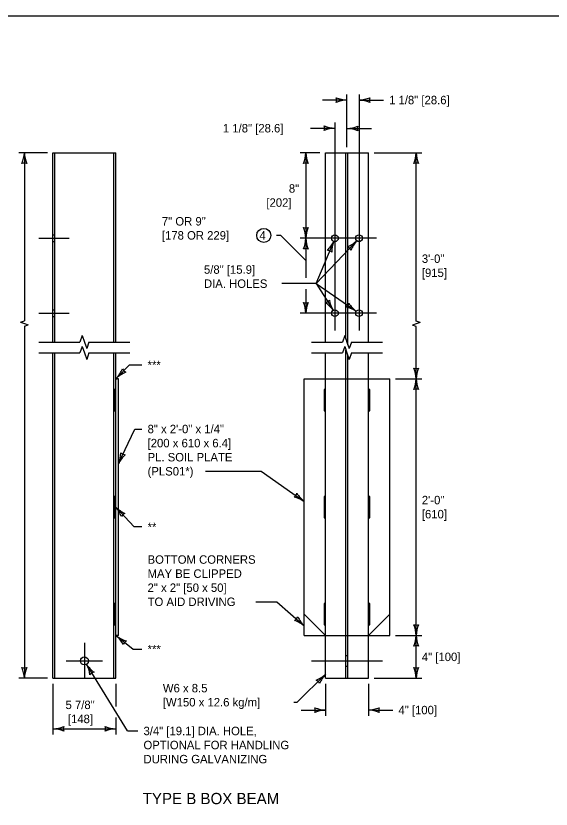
# Model space of a CAD drawing. Extents: x 49991.4 to 50021, y 49987.6 to 50011.4.
# Drawn here: x 50004.46 to 50008.26, y 49993.37 to 49999 of the extents above; entities that cross this region are included whole.
import ezdxf

# ---------------------------------------------------------------- set-up
doc = ezdxf.new("R2010")
doc.units = 0
for name, color, linetype in [('Level 1', 7, 'Continuous'), ('Level 2', 7, 'Continuous'), ('Level 3', 7, 'Continuous'), ('Level 4', 7, 'Continuous'), ('Level 5', 7, 'Continuous'), ('Level 6', 7, 'Continuous')]:
    doc.layers.add(name, color=color, linetype=linetype)

msp = doc.modelspace()

# ---------------------------------------------------------------- linework, layer by layer
at = {"layer": 'Level 1'}
for p, q in [((50004.7193, 49998.0275), (50005.1652, 49998.0275)), ((50004.7193, 49996.6835), (50004.7193, 49998.0275)), ((50004.7335, 49996.6835), (50004.7335, 49998.0275)), ((50005.151, 49996.6835), (50005.151, 49998.0275)), ((50005.1652, 49996.6835), (50005.1652, 49998.0275)), ((50006.6543, 49998.0275), (50006.9579, 49998.0275)), ((50006.6543, 49996.6835), (50006.6543, 49998.0275)), ((50006.9579, 49996.6835), (50006.9579, 49998.0275)), ((50004.7193, 49994.2976), (50004.7193, 49996.6067)), ((50004.7335, 49994.2976), (50004.7335, 49996.6067)), ((50005.151, 49994.2976), (50005.151, 49996.6067)), ((50005.1652, 49994.2976), (50005.1652, 49996.6067)), ((50006.6543, 49994.2976), (50006.6543, 49996.6067)), ((50006.9579, 49994.2976), (50006.9579, 49996.6067)), ((50005.1842, 49996.4228), (50005.1652, 49996.4228)), ((50005.1842, 49994.6012), (50005.1842, 49996.4228)), ((50006.5025, 49994.6012), (50006.5025, 49996.4228)), ((50006.5025, 49996.4228), (50006.6543, 49996.4228)), ((50006.9579, 49996.4228), (50007.1097, 49996.4228)), ((50007.1097, 49994.6012), (50007.1097, 49996.4228)), ((50005.1652, 49996.3469), (50005.1555, 49996.3469)), ((50005.1555, 49996.3469), (50005.1555, 49996.1951)), ((50005.1652, 49996.1951), (50005.1652, 49996.3469)), ((50006.6543, 49996.3469), (50006.6446, 49996.3469)), ((50006.6446, 49996.3469), (50006.6446, 49996.1951)), ((50006.6543, 49996.1951), (50006.6543, 49996.3469)), ((50006.9677, 49996.3469), (50006.9579, 49996.3469)), ((50006.9579, 49996.3469), (50006.9579, 49996.1951)), ((50006.9677, 49996.1951), (50006.9677, 49996.3469)), ((50005.1555, 49996.1951), (50005.1652, 49996.1951)), ((50006.6446, 49996.1951), (50006.6543, 49996.1951)), ((50006.9579, 49996.1951), (50006.9677, 49996.1951)), ((50005.1652, 49995.5879), (50005.1555, 49995.5879)), ((50005.1555, 49995.5879), (50005.1555, 49995.4361)), ((50005.1652, 49995.4361), (50005.1652, 49995.5879)), ((50006.6543, 49995.5879), (50006.6446, 49995.5879)), ((50006.6446, 49995.5879), (50006.6446, 49995.4361)), ((50006.6543, 49995.4361), (50006.6543, 49995.5879)), ((50006.9677, 49995.5879), (50006.9579, 49995.5879)), ((50006.9579, 49995.5879), (50006.9579, 49995.4361)), ((50006.9677, 49995.4361), (50006.9677, 49995.5879)), ((50005.1555, 49995.4361), (50005.1652, 49995.4361)), ((50006.6446, 49995.4361), (50006.6543, 49995.4361)), ((50006.9579, 49995.4361), (50006.9677, 49995.4361)), ((50005.1652, 49994.8289), (50005.1555, 49994.8289)), ((50005.1555, 49994.8289), (50005.1555, 49994.6771)), ((50005.1652, 49994.6771), (50005.1652, 49994.8289)), ((50006.6543, 49994.8289), (50006.6446, 49994.8289)), ((50006.6446, 49994.8289), (50006.6446, 49994.6771)), ((50006.6543, 49994.6771), (50006.6543, 49994.8289)), ((50006.9677, 49994.8289), (50006.9579, 49994.8289)), ((50006.9579, 49994.8289), (50006.9579, 49994.6771)), ((50006.9677, 49994.6771), (50006.9677, 49994.8289)), ((50005.1555, 49994.6771), (50005.1652, 49994.6771)), ((50006.6446, 49994.6771), (50006.6543, 49994.6771)), ((50006.9579, 49994.6771), (50006.9677, 49994.6771)), ((50005.1842, 49994.6012), (50005.1652, 49994.6012)), ((50006.5025, 49994.6012), (50006.6543, 49994.6012)), ((50006.9579, 49994.6012), (50007.1097, 49994.6012)), ((50004.7193, 49994.2976), (50005.1652, 49994.2976)), ((50006.6543, 49994.2976), (50006.9579, 49994.2976))]:
    msp.add_line(p, q, dxfattribs=at)
msp.add_lwpolyline([(49999.3835, 49998.9992), (50016.7501, 49998.9992), (50016.7501, 49987.7988), (49999.3835, 49987.7988)], close=True, dxfattribs=at)
for points in [[(50005.1652, 49996.4325), (50005.1652, 49996.4228), (50005.1749, 49996.4228), (50005.1652, 49996.4325)], [(50005.1652, 49994.5915), (50005.1652, 49994.6012), (50005.1749, 49994.6012), (50005.1652, 49994.5915)]]:
    msp.add_lwpolyline(points, dxfattribs=at)
for centre, radius in [((50006.7207, 49997.4203), 0.0237), ((50006.8915, 49997.4203), 0.0237), ((50006.7207, 49996.889), 0.0237), ((50006.8915, 49996.889), 0.0237), ((50004.9424, 49994.4207), 0.0285)]:
    msp.add_circle(centre, radius, dxfattribs=at)
at = {"layer": 'Level 2'}
msp.add_circle((50006.2154, 49997.4409), 0.05, dxfattribs=at)
at = {"layer": 'Level 3'}
for p, q in [((50006.8061, 49998.4017), (50006.6327, 49998.4017)), ((50006.8061, 49998.0675), (50006.8061, 49998.4417)), ((50006.8915, 49998.4017), (50007.065, 49998.4017)), ((50006.5473, 49998.2017), (50006.7207, 49998.2017)), ((50006.8061, 49998.1999), (50006.9796, 49998.1999)), ((50004.6793, 49998.0275), (50004.4761, 49998.0275)), ((50004.5161, 49998.0275), (50004.5161, 49996.8346)), ((50006.6143, 49998.0275), (50006.4743, 49998.0275)), ((50006.5143, 49998.0275), (50006.5143, 49997.4203)), ((50006.9979, 49998.0275), (50007.3375, 49998.0275)), ((50007.2975, 49996.8331), (50007.2975, 49998.0275)), ((50006.3366, 49997.4409), (50006.3054, 49997.4409)), ((50006.5143, 49997.2632), (50006.3366, 49997.4409)), ((50006.5143, 49997.4203), (50006.5143, 49997.1384)), ((50006.5864, 49997.0984), (50006.8752, 49997.4031)), ((50006.5864, 49997.0984), (50006.7116, 49997.3985)), ((50006.5864, 49997.0984), (50006.3443, 49997.0984)), ((50006.5143, 49997.0584), (50006.5143, 49996.889)), ((50006.5864, 49997.0984), (50006.7079, 49996.909)), ((50006.5864, 49997.0984), (50006.872, 49996.9025)), ((50004.4887, 49996.8249), (50004.5161, 49996.8346)), ((50004.4887, 49996.8249), (50004.5161, 49996.8152)), ((50007.3249, 49996.8234), (50007.2975, 49996.8331)), ((50007.3249, 49996.8234), (50007.2975, 49996.8137)), ((50004.5161, 49996.8152), (50004.5435, 49996.8055)), ((50004.5161, 49996.7958), (50004.5435, 49996.8055)), ((50004.5161, 49996.7958), (50004.5161, 49994.2976)), ((50007.2975, 49996.8137), (50007.2701, 49996.804)), ((50007.2975, 49996.7943), (50007.2701, 49996.804)), ((50007.2975, 49996.4228), (50007.2975, 49996.7943)), ((50005.2635, 49996.521), (50005.1701, 49996.4276)), ((50005.2635, 49996.521), (50005.3508, 49996.521)), ((50007.1497, 49996.4228), (50007.3375, 49996.4228)), ((50007.2975, 49994.6012), (50007.2975, 49996.4228)), ((50005.1842, 49995.8213), (50005.2992, 49996.0664)), ((50005.2992, 49996.0664), (50005.3508, 49996.0664)), ((50005.8029, 49995.7664), (50006.1966, 49995.7664)), ((50006.1966, 49995.7664), (50006.5025, 49995.5529)), ((50005.1652, 49995.512), (50005.296, 49995.3709)), ((50005.3508, 49995.3709), (50005.296, 49995.3709)), ((50006.1581, 49994.8399), (50006.3088, 49994.8399)), ((50006.3088, 49994.8399), (50006.5025, 49994.6701)), ((50005.2867, 49994.5041), (50005.1701, 49994.5963)), ((50007.1497, 49994.6012), (50007.3375, 49994.6012)), ((50007.2975, 49994.2976), (50007.2975, 49994.6012)), ((50005.2867, 49994.5041), (50005.3508, 49994.5041)), ((50005.248, 49993.9229), (50004.9572, 49994.3965)), ((50004.6793, 49994.2976), (50004.4761, 49994.2976)), ((50006.4521, 49994.127), (50006.6543, 49994.3256)), ((50006.9979, 49994.2976), (50007.3375, 49994.2976)), ((50004.7193, 49994.2576), (50004.7193, 49993.8983)), ((50005.1652, 49994.2576), (50005.1652, 49994.0977)), ((50006.6543, 49994.2576), (50006.6543, 49994.0314)), ((50006.9579, 49994.2576), (50006.9579, 49994.0314)), ((50006.4292, 49994.127), (50006.4521, 49994.127)), ((50006.4809, 49994.0714), (50006.6543, 49994.0714)), ((50006.9979, 49994.0714), (50007.1314, 49994.0714)), ((50005.1652, 49994.0177), (50005.1652, 49993.8983)), ((50004.7193, 49993.9383), (50005.1652, 49993.9383)), ((50005.248, 49993.9229), (50005.3217, 49993.9229))]:
    msp.add_line(p, q, dxfattribs=at)
for centre, radius, start, end in [((50006.6779, 49998.4017), 0.0548, 342.1388, 17.8612), ((50006.8176, 49998.6344), 0.233, 247.9228, 267.1727), ((50006.8153, 49998.1795), 0.2223, 92.3605, 112.544), ((50006.88, 49998.6344), 0.233, 272.8273, 292.0772), ((50006.8824, 49998.1795), 0.2223, 67.456, 87.6395), ((50007.0197, 49998.4017), 0.0548, 162.1388, 197.8612), ((50006.7299, 49998.4238), 0.2223, 247.456, 267.6395), ((50006.5925, 49998.2017), 0.0548, 342.1388, 17.8612), ((50006.7322, 49997.969), 0.233, 92.8273, 112.0772), ((50006.7946, 49998.4327), 0.233, 272.8273, 292.0772), ((50006.797, 49997.9778), 0.2223, 67.456, 87.6395), ((50006.9343, 49998.1999), 0.0548, 162.1388, 197.8612), ((50004.2834, 49998.039), 0.233, 337.9228, 357.1727), ((50004.7382, 49998.0367), 0.2223, 182.3605, 202.544), ((50006.2922, 49998.0367), 0.2223, 337.456, 357.6395), ((50006.747, 49998.039), 0.233, 182.8273, 202.0772), ((50007.0753, 49998.0367), 0.2223, 337.456, 357.6395), ((50007.5302, 49998.039), 0.233, 182.8273, 202.0772), ((50004.5161, 49997.8993), 0.0548, 72.1388, 107.8612), ((50006.5143, 49997.8993), 0.0548, 72.1388, 107.8612), ((50007.2975, 49997.8993), 0.0548, 72.1388, 107.8612), ((50006.5143, 49997.5486), 0.0548, 252.1388, 287.8612), ((50006.2816, 49997.4089), 0.233, 2.8273, 22.0772), ((50006.7365, 49997.4112), 0.2223, 157.456, 177.6395), ((50006.2922, 49997.4295), 0.2223, 337.456, 357.6395), ((50006.747, 49997.4318), 0.233, 182.8273, 202.0772), ((50006.5101, 49997.4925), 0.2223, 314.8029, 334.9864), ((50006.9308, 49997.3194), 0.233, 160.1742, 179.4241), ((50006.7203, 49997.5626), 0.2223, 293.989, 314.1725), ((50007.052, 49997.2514), 0.233, 139.3603, 158.6102), ((50006.5143, 49997.2921), 0.0548, 72.1388, 107.8612), ((50006.6622, 49997.2801), 0.0548, 49.4857, 85.2081), ((50006.787, 49997.3101), 0.0548, 28.6718, 64.3942), ((50006.5143, 49997.0173), 0.0548, 252.1388, 287.8612), ((50006.2816, 49996.8776), 0.233, 2.8273, 22.0772), ((50006.7365, 49996.8799), 0.2223, 157.456, 177.6395), ((50006.6387, 49997.0169), 0.0548, 284.8216, 320.544), ((50006.5183, 49996.7737), 0.233, 35.5101, 54.76), ((50006.8998, 49997.0212), 0.2223, 190.1388, 210.3223), ((50006.7663, 49996.975), 0.0548, 307.6774, 343.3997), ((50007.0052, 49997.0804), 0.2223, 212.9945, 233.1781), ((50006.7498, 49996.7041), 0.233, 58.3658, 77.6157), ((50004.9974, 49996.5841), 0.233, 317.8273, 337.0772), ((50005.2607, 49996.5183), 0.0548, 207.1388, 242.8612), ((50007.2975, 49996.551), 0.0548, 252.1388, 287.8612), ((50007.0647, 49996.4113), 0.233, 2.8273, 22.0772), ((50007.5196, 49996.4136), 0.2223, 157.456, 177.6395), ((50005.3207, 49996.2641), 0.2223, 112.456, 132.6395), ((50007.0753, 49996.4319), 0.2223, 337.456, 357.6395), ((50007.5302, 49996.4343), 0.233, 182.8273, 202.0772), ((50007.2975, 49996.2946), 0.0548, 72.1388, 107.8612), ((50004.9686, 49995.9097), 0.233, 337.6883, 356.9381), ((50005.3814, 49995.7186), 0.2223, 132.317, 152.5005), ((50005.2387, 49995.9373), 0.0548, 226.9998, 262.7222), ((50006.3974, 49995.6263), 0.0548, 307.2321, 342.9545), ((50006.3788, 49995.3555), 0.233, 57.9206, 77.1705), ((50006.6371, 49995.7299), 0.2223, 212.5493, 232.7328), ((50004.9961, 49995.3677), 0.2223, 20.2956, 40.4791), ((50005.328, 49995.6786), 0.233, 225.6669, 244.9168), ((50005.2524, 49995.418), 0.0548, 114.9784, 150.7008), ((50006.4061, 49994.7546), 0.0548, 300.8978, 336.6202), ((50006.3578, 49994.4875), 0.233, 51.5863, 70.8362), ((50006.6558, 49994.8311), 0.2223, 206.215, 226.3985), ((50007.2975, 49994.7294), 0.0548, 252.1388, 287.8612), ((50007.0647, 49994.5897), 0.233, 2.8273, 22.0772), ((50007.5196, 49994.592), 0.2223, 157.456, 177.6395), ((50005.0251, 49994.4278), 0.2223, 29.1213, 49.3048), ((50005.3054, 49994.786), 0.233, 234.4926, 253.7425), ((50007.0753, 49994.6103), 0.2223, 337.456, 357.6395), ((50007.5302, 49994.6127), 0.233, 182.8273, 202.0772), ((50005.2706, 49994.5168), 0.0548, 123.8041, 159.5265), ((50007.2975, 49994.473), 0.0548, 72.1388, 107.8612), ((50004.294, 49994.2884), 0.2223, 2.3605, 22.544), ((50004.5161, 49994.4258), 0.0548, 252.1388, 287.8612), ((50004.7488, 49994.2861), 0.233, 157.9228, 177.1727), ((50004.7618, 49994.2905), 0.2223, 8.27, 28.4536), ((50005.1512, 49994.5255), 0.233, 213.6413, 232.8912), ((50007.2975, 49994.4258), 0.0548, 252.1388, 287.8612), ((50007.0647, 49994.2861), 0.233, 2.8273, 22.0772), ((50007.5196, 49994.2884), 0.2223, 157.456, 177.6395), ((50005.0229, 49994.2863), 0.0548, 102.9529, 138.6752), ((50006.5052, 49994.4905), 0.2223, 291.9435, 312.127), ((50006.8256, 49994.1676), 0.233, 137.3148, 156.5646), ((50006.5629, 49994.2357), 0.0548, 26.6263, 62.3487), ((50006.6635, 49994.2935), 0.2223, 247.456, 267.6395), ((50006.5261, 49994.0714), 0.0548, 342.1388, 17.8612), ((50006.6658, 49993.8387), 0.233, 92.8273, 112.0772), ((50006.9465, 49994.3041), 0.233, 272.8273, 292.0772), ((50006.9488, 49993.8492), 0.2223, 67.456, 87.6395), ((50007.0862, 49994.0714), 0.0548, 162.1388, 197.8612), ((50004.7078, 49994.171), 0.233, 272.8273, 292.0772), ((50004.8475, 49993.9383), 0.0548, 162.1388, 197.8612), ((50005.1744, 49994.1604), 0.2223, 247.456, 267.6395), ((50005.037, 49993.9383), 0.0548, 342.1388, 17.8612), ((50004.7101, 49993.7162), 0.2223, 67.456, 87.6395), ((50005.1767, 49993.7056), 0.233, 92.8273, 112.0772)]:
    msp.add_arc(centre, radius, start, end, dxfattribs=at)
at = {"layer": 'Level 4'}
for p, q in [((50006.799, 49996.7036), (50006.799, 49998.0275)), ((50006.8132, 49996.6634), (50006.8132, 49998.0275)), ((50004.7193, 49997.4441), (50004.7335, 49997.4441)), ((50004.7193, 49997.3966), (50004.7335, 49997.3966)), ((50004.7193, 49996.9128), (50004.7335, 49996.9128)), ((50004.7193, 49996.8653), (50004.7335, 49996.8653)), ((50006.799, 49994.2976), (50006.799, 49996.6268)), ((50006.8132, 49994.2976), (50006.8132, 49996.5866)), ((50006.6543, 49996.4228), (50006.9579, 49996.4228)), ((50006.5025, 49994.753), (50006.6543, 49994.6012)), ((50006.9579, 49994.6012), (50007.1097, 49994.753)), ((50006.6543, 49994.6012), (50006.9579, 49994.6012)), ((50006.799, 49994.4583), (50006.8132, 49994.4583)), ((50006.799, 49994.3833), (50006.8132, 49994.3833))]:
    msp.add_line(p, q, dxfattribs=at)
at = {"layer": 'Level 5'}
for p, q in [((50006.8915, 49998.4417), (50006.8915, 49996.7653)), ((50006.7207, 49998.2417), (50006.7207, 49996.7653)), ((50004.6193, 49997.4203), (50004.8335, 49997.4203)), ((50007.0152, 49997.4203), (50006.4743, 49997.4203)), ((50004.6193, 49996.889), (50004.8335, 49996.889)), ((50007.0152, 49996.889), (50006.4743, 49996.889)), ((50004.9424, 49994.5492), (50004.9424, 49994.2922)), ((50004.8139, 49994.4207), (50005.0708, 49994.4207)), ((50006.5543, 49994.4208), (50007.0579, 49994.4208))]:
    msp.add_line(p, q, dxfattribs=at)
at = {"layer": 'Level 6'}
for p, q in [((50004.9261, 49996.7292), (50004.9099, 49996.6835)), ((50004.9261, 49996.7292), (50004.9423, 49996.6835)), ((50006.7899, 49996.7292), (50006.7737, 49996.6835)), ((50006.7899, 49996.7292), (50006.8061, 49996.6835)), ((50004.6193, 49996.6835), (50004.9099, 49996.6835)), ((50004.9261, 49996.6524), (50004.9099, 49996.6067)), ((50004.9261, 49996.6524), (50004.9423, 49996.6067)), ((50004.9423, 49996.6835), (50004.9585, 49996.6378)), ((50004.9747, 49996.6835), (50004.9585, 49996.6378)), ((50004.9747, 49996.6835), (50005.2652, 49996.6835)), ((50006.5543, 49996.6835), (50006.7737, 49996.6835)), ((50006.7899, 49996.6524), (50006.7737, 49996.6067)), ((50006.7899, 49996.6524), (50006.8061, 49996.6067)), ((50006.8061, 49996.6835), (50006.8223, 49996.6378)), ((50006.8385, 49996.6835), (50006.8223, 49996.6378)), ((50006.8385, 49996.6835), (50007.0579, 49996.6835)), ((50004.6193, 49996.6067), (50004.9099, 49996.6067)), ((50004.9423, 49996.6067), (50004.9585, 49996.561)), ((50004.9747, 49996.6067), (50004.9585, 49996.561)), ((50004.9747, 49996.6067), (50005.2652, 49996.6067)), ((50006.5543, 49996.6067), (50006.7737, 49996.6067)), ((50006.8061, 49996.6067), (50006.8223, 49996.561)), ((50006.8385, 49996.6067), (50006.8223, 49996.561)), ((50006.8385, 49996.6067), (50007.0579, 49996.6067))]:
    msp.add_line(p, q, dxfattribs=at)

# ---------------------------------------------------------------- texts
at = {"layer": 'Level 2'}
for s, height, p in [('1 1/8" [28.6]', 0.06, (50007.105, 49998.3717)), ('1 1/8" [28.6]', 0.06, (50005.9252, 49998.1717)), ('7" OR 9"', 0.06, (50005.4923, 49997.5109)), ('[178 OR 229]', 0.06, (50005.4923, 49997.4109)), ('4', 0.06, (50006.185, 49997.4109)), ('3\'-0"', 0.06, (50007.3375, 49997.2455)), ('5/8" [15.9]', 0.06, (50005.7909, 49997.1684)), ('[915]', 0.06, (50007.3375, 49997.1455)), ('DIA. HOLES', 0.06, (50005.7909, 49997.0684)), ('***', 0.06, (50005.3908, 49996.491)), ('8" x 2\'-0" x 1/4"', 0.06, (50005.3908, 49996.0364)), ('[200 x 610 x 6.4]', 0.06, (50005.3908, 49995.9364)), ('PL. SOIL PLATE', 0.06, (50005.3908, 49995.8364)), ('(PLS01*)', 0.06, (50005.3908, 49995.7364)), ('2\'-0"', 0.06, (50007.3375, 49995.532)), ('[610]', 0.06, (50007.3375, 49995.432)), ('**', 0.06, (50005.3908, 49995.3409)), ('BOTTOM CORNERS', 0.06, (50005.3908, 49995.1099)), ('MAY BE CLIPPED', 0.06, (50005.3908, 49995.0099)), ('2" x 2" [50 x 50]', 0.06, (50005.3908, 49994.9099)), ('TO AID DRIVING', 0.06, (50005.3908, 49994.8099)), ('***', 0.06, (50005.3908, 49994.4741)), ('4" [100]', 0.06, (50007.3375, 49994.4189)), ('W6 x 8.5', 0.06, (50005.4992, 49994.197)), ('[W150 x 12.6 kg/m]', 0.06, (50005.4992, 49994.097)), ('3/4" [19.1] DIA. HOLE,', 0.06, (50005.3617, 49993.893)), ('OPTIONAL FOR HANDLING', 0.06, (50005.3617, 49993.793)), ('DURING GALVANIZING', 0.06, (50005.3617, 49993.693)), ('TYPE B BOX BEAM ', 0.08, (50005.3562, 49993.4033))]:
    msp.add_text(s, height=height, dxfattribs=at).set_placement(p)
for s, p in [('8"', (50006.3936, 49997.7439)), ('[202]', (50006.2339, 49997.6439)), ('5 7/8"', (50004.8083, 49994.0783)), ('4" [100]', (50007.1714, 49994.0414)), ('[148]', (50004.8251, 49993.9783))]:
    msp.add_text(s, height=0.06, rotation=360, dxfattribs=at).set_placement(p)

doc.saveas('drawing.dxf')
